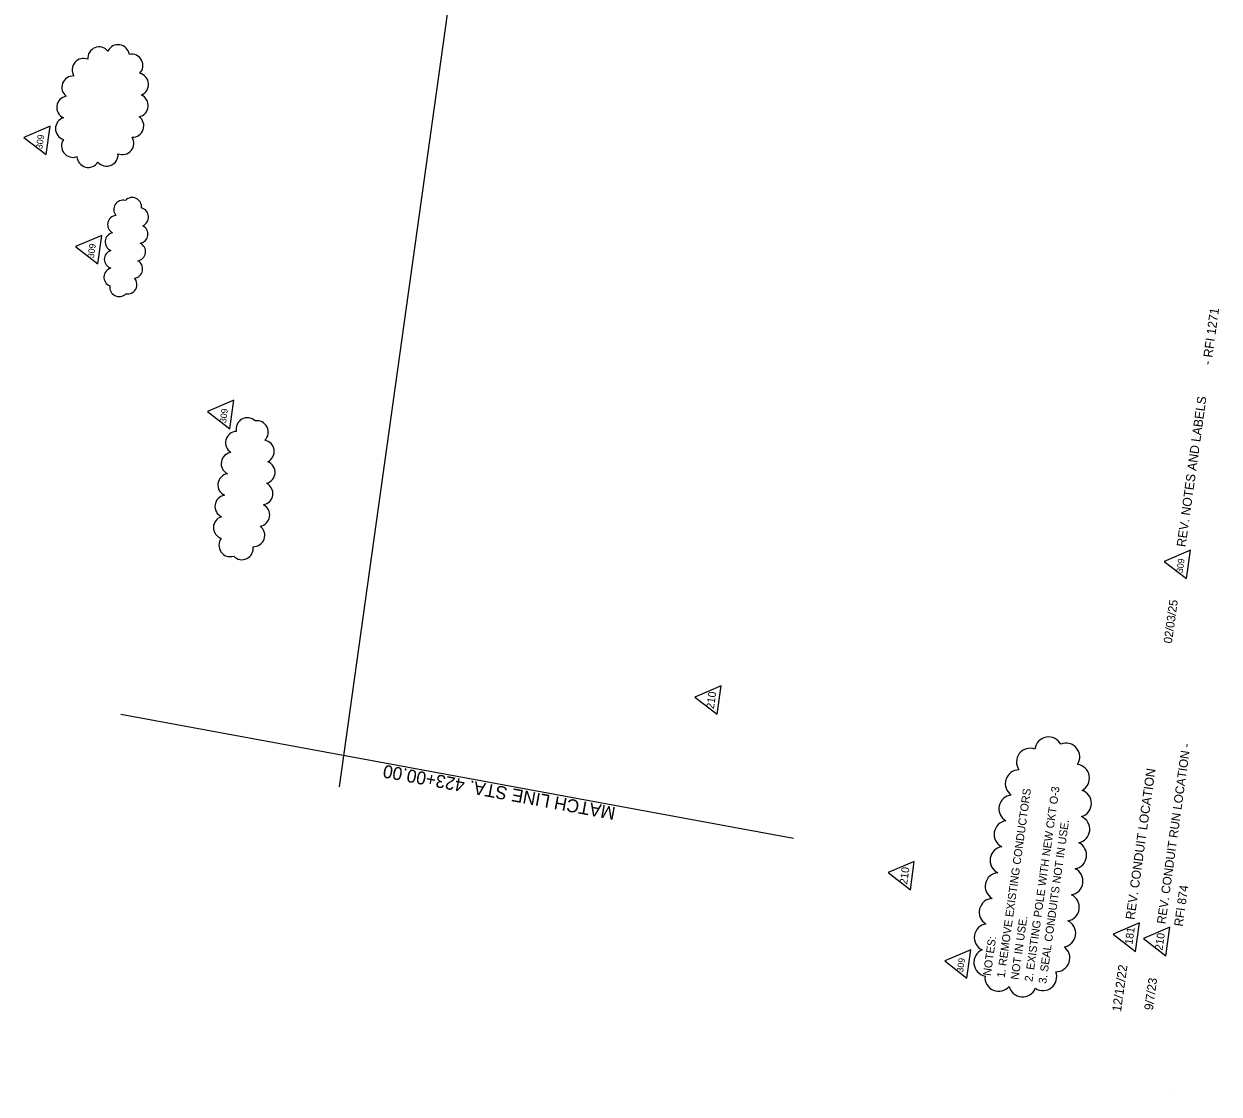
# Model space of a CAD drawing. Extents: x 930268 to 931132, y 618295 to 619577.
# Drawn here: x 930268 to 931005, y 618295 to 618955 of the extents above; entities that cross this region are included whole.
import ezdxf

# ---------------------------------------------------------------- set-up
doc = ezdxf.new("R2010")
doc.units = 0
for name, color, linetype in [('ActivePointCell_dp', 7, 'Continuous'), ('AdhocPoint_dp', 7, 'Continuous'), ('Cloud_dp', 7, 'Continuous'), ('MatchLines_dp', 7, 'Continuous'), ('TextLabel', 7, 'Continuous'), ('TextMinor', 7, 'Continuous')]:
    doc.layers.add(name, color=color, linetype=linetype)

msp = doc.modelspace()

# ---------------------------------------------------------------- linework, layer by layer
at = {"layer": 'ActivePointCell_dp'}
msp.add_line((930462.95, 618484.75), (930615.71, 619576.99), dxfattribs=at)
at = {"layer": 'AdhocPoint_dp'}
msp.add_line((930977.73, 618295.31), (930977.73, 618295.31), dxfattribs=at)
at = {"layer": 'Cloud_dp'}
for points in [[(930268.37, 618885), (930282.07, 618874.38), (930284.52, 618891.86)], [(930300.18, 618817.78), (930313.88, 618807.16), (930316.33, 618824.64)], [(930381.67, 618716.09), (930395.38, 618705.47), (930397.82, 618722.95)], [(930971.64, 618623.67), (930985.34, 618613.05), (930987.79, 618630.53)], [(930682.17, 618540.05), (930695.87, 618529.43), (930698.32, 618546.91)], [(930801.33, 618431.86), (930815.04, 618421.24), (930817.48, 618438.72)], [(930940.16, 618393.92), (930953.86, 618383.3), (930956.31, 618400.78)], [(930958.81, 618391.25), (930972.51, 618380.63), (930974.96, 618398.11)], [(930836.22, 618377.46), (930849.93, 618366.84), (930852.38, 618384.32)]]:
    msp.add_lwpolyline(points, close=True, dxfattribs=at)
for centre, radius, start, end in [((930314.78, 618933.75), 7.02, 39.80271, 184.80271), ((930326.46, 618935.13), 7.02, 8.70111, 153.70111), ((930334.78, 618929.31), 7.02, 316.33355, 101.33355), ((930305.12, 618926.67), 7.02, 67.67908, 212.67908), ((930298.78, 618915.87), 7.02, 86.4837, 231.4837), ((930338.21, 618917.64), 7.02, 291.4788, 76.4788), ((930295.64, 618903.47), 7.02, 100.15938, 245.15938), ((930338.03, 618904.66), 7.02, 281.87117, 66.87117), ((930294.87, 618890.43), 7.02, 108.00995, 253.00995), ((930335.3, 618892.14), 7.02, 268.50573, 53.50573), ((930329.15, 618881.42), 7.02, 246.88046, 31.88046), ((930298.6, 618879.74), 7.02, 145.52957, 290.52957), ((930308.07, 618873.55), 7.02, 183.07468, 328.07468), ((930319.4, 618874.35), 7.02, 220.00065, 5.00065), ((930335.18, 618842.26), 5.73, 352.30551, 137.30551), ((930329.49, 618840.61), 5.73, 74.98402, 219.98402), ((930339.52, 618835.93), 5.73, 291.48796, 76.48796), ((930325.73, 618831.24), 5.73, 96.38413, 241.38413), ((930324.18, 618820.61), 5.73, 101.97917, 246.97917), ((930339.16, 618825.42), 5.73, 279.53834, 64.53834), ((930337.64, 618814.6), 5.73, 279.53834, 64.53834), ((930323.69, 618809.88), 5.73, 107.84258, 252.84258), ((930323.43, 618798.86), 5.73, 104.38433, 249.38433), ((930335.86, 618803.92), 5.73, 276.54319, 61.54319), ((930332.36, 618794.29), 5.73, 258.44285, 43.44285), ((930327.07, 618792.63), 5.72, 171.29831, 316.29831), ((930406.19, 618705.22), 7, 46.70842, 191.70842), ((930412.07, 618703.39), 7, 313.90424, 98.90424), ((930399.75, 618696.81), 7, 93.359, 238.359), ((930415.77, 618691.44), 7, 295.50073, 80.50073), ((930397.03, 618683.91), 7, 97.80892, 242.80892), ((930416.25, 618678.6), 7, 283.80542, 68.80542), ((930394.99, 618670.78), 7, 99.53834, 244.53834), ((930414.92, 618665.48), 7, 279.53834, 64.53834), ((930393.19, 618657.56), 7, 99.9807, 244.9807), ((930413, 618652.28), 7, 278.95656, 63.95656), ((930392.27, 618644.52), 7, 106.96127, 251.96127), ((930409.93, 618639.74), 7, 268.51135, 53.51135), ((930395.65, 618633.59), 7, 142.33618, 287.33618), ((930402.82, 618631.72), 7, 223.39507, 8.39507), ((930888.95, 618500), 8.49, 69.88472, 214.88472), ((930900.31, 618506.96), 8.49, 28.0967, 173.0967), ((930911.01, 618503.09), 8.49, 327.23081, 112.23081), ((930882.06, 618486.65), 8.49, 90.47438, 235.47438), ((930917.01, 618490.08), 8.49, 297.2721, 82.2721), ((930878.1, 618471.2), 8.49, 95.76515, 240.76515), ((930918.21, 618474.48), 8.49, 286.46933, 71.46933), ((930917.21, 618458.55), 8.49, 281.38827, 66.38827), ((930875.18, 618455.39), 8.49, 98.35846, 243.35846), ((930915.24, 618442.55), 8.49, 279.5478, 64.5478), ((930872.66, 618439.4), 8.49, 98.6655, 243.6655), ((930869.67, 618423.33), 8.49, 95.29695, 240.29695), ((930913, 618426.51), 8.49, 279.53834, 64.53834), ((930866, 618407.47), 8.49, 93.62707, 238.62707), ((930910.75, 618410.46), 8.49, 279.53834, 64.53834), ((930862.97, 618391.84), 8.49, 99.42292, 244.42292), ((930908.51, 618394.42), 8.49, 279.53834, 64.53834), ((930862.73, 618376.41), 8.5, 113.8002, 258.8002), ((930904.89, 618379.19), 8.49, 268.73884, 53.73884), ((930896.8, 618367.59), 8.49, 236.46853, 21.46853), ((930869.53, 618367.21), 8.49, 174.17907, 319.17907), ((930884.21, 618363.64), 8.49, 193.42133, 338.42133)]:
    msp.add_arc(centre, radius, start, end, dxfattribs=at)
at = {"layer": 'MatchLines_dp'}
msp.add_line((930742.89, 618452.95), (930328.18, 618529.39), dxfattribs=at)

# ---------------------------------------------------------------- texts
at = {"layer": 'Cloud_dp'}
for s, height, p in [('309', 4, (930279.69, 618877.63)), ('309', 4, (930311.5, 618810.4)), ('309', 4, (930392.99, 618708.71)), ('309', 4, (930982.96, 618616.29)), ('210', 4.799, (930693.87, 618532.49)), ('210', 4.799, (930813.03, 618424.31)), ('181', 4.799, (930951.98, 618387.24)), ('210', 4.799, (930970.51, 618383.69)), ('309', 4, (930847.55, 618370.08))]:
    msp.add_text(s, height=height, rotation=82.03834, dxfattribs=at).set_placement(p)
at = {"layer": 'MatchLines_dp'}
msp.add_text('MATCH LINE STA. 423+00.00', height=8, rotation=169.55632, dxfattribs=at).set_placement((930633.68, 618472.1))
at = {"layer": 'TextLabel'}
for s, height, p in [('1. REMOVE EXISTING CONDUCTORS', 4.9355, (930873.18, 618366.77)), ('2. EXISTING POLE WITH NEW CKT O-3', 4.9355, (930890.29, 618364.38)), ('3. SEAL CONDUITS NOT IN USE.', 4.9355, (930898.84, 618363.18)), ('NOT IN USE.', 4.9355, (930881.73, 618365.57)), ('NOTES:', 4.936, (930864.62, 618367.96))]:
    msp.add_text(s, height=height, rotation=82.04669, dxfattribs=at).set_placement(p)
at = {"layer": 'TextMinor'}
for s, height, p in [('- RFI 1271', 5.6, (931000.58, 618744.52)), ('REV. NOTES AND LABELS', 5.6, (930984.73, 618632.31)), ('02/03/25', 5.2, (930976.28, 618572.85)), ('REV. CONDUIT RUN LOCATION - ', 5.376, (930972.33, 618399.9)), ('REV. CONDUIT LOCATION', 5.6, (930953.24, 618402.57)), ('RFI 874', 5.376, (930982.97, 618398.41)), ('12/12/22', 5.6, (930944.93, 618345.79)), ('9/7/23', 5.376, (930964.53, 618346.74))]:
    msp.add_text(s, height=height, rotation=82.03834, dxfattribs=at).set_placement(p)

doc.saveas('drawing.dxf')
